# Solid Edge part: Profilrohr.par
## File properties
Username: bmolnar
Dokumentum tartalom típus: 0
Author: bmolnar
Last saved by: bmolnar
Revision: 94
Sűrűség: 0,000 kg/m^3
Pontosság: 0,990
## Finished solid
Body 1: solid body, 179 faces, 530 edges, 352 vertices.
  Faces by surface: cylinder 109, plane 70
  Edges by curve: line 312, circle 218
Bounding box of the edges (mm): 105.500 x 105.500 x 1557.000, from (-52.75, -52.75, -1516) to (52.75, 52.75, 41).
Cylindrical faces by radius (mm): R0.1 x16, R0.2 x30, R0.5 x28, R1 x10, R4.6 x8, R5.7 x4, R7.5 x4, R50 x1, R52.7 x8
Planar faces by outward normal: +x 6, +y 6, +z 1, -x 4, -y 4, -z 1, oblique 48
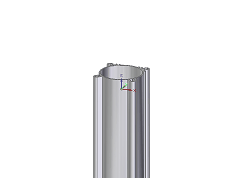
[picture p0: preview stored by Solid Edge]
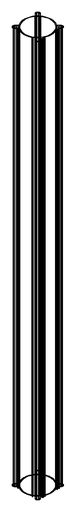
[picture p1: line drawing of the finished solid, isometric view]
